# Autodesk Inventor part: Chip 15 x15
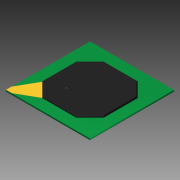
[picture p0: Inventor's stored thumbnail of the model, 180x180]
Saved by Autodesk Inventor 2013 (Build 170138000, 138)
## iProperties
Company: Autodesk Inc.
Created: 2005-12
Part Number: Chip 15 x15
Document SubType Name: Modeling
Designer: Autodesk Inc.
Density: 1 g/cm^3
Mass: 0.665599 g
Surface Area: 18.8536 cm^2
Volume: 0.665599 cm^3
Material: Allgemein
Title: Personal Computer
Author: Autodesk Inc.
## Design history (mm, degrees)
sketch "Sketch1"
  geometry: L1 (0, 21)-(0, -21) reference; L2 (-21, 0)-(21, 0) reference; L3 (-15, 15)-(15, 15); L4 (15, 15)-(15, -15); L5 (15, -15)-(-15, -15); L6 (-15, -15)-(-15, 15)
  constraints: 8 end point, 2 parallel, 2 perpendicular, 1 horizontal, 2 other
  dimensions: "d0" = 30 distance of L3.start L3.end
extrude "Extrusion1" new body sketch "Sketch1" distance "d1" = 0.5; taper "d2" = 0 deg
sketch "Sketch2"
  geometry: L1 (0, 21)-(0, -21) reference; L2 (-21, 0)-(21, 0) reference; L3 (-11, 11)-(11, 11); L4 (11, 11)-(11, -11); L5 (11, -11)-(-11, -11); L6 (-11, -11)-(-11, 11)
  constraints: 8 end point, 2 parallel, 2 perpendicular, 1 horizontal, 2 other
  dimensions: "d3" = 22 distance of L3.start L3.end
extrude "Extrusion2" join sketch "Sketch2" distance "d4" = 0.5; taper "d5" = 0 deg
chamfer "Chamfer1" distance "d6" = 5; stored, may be unused: second distance "d7" = 2, angle "d8" = 45 deg
chamfer "Chamfer2" distance "d9" = 0.3; stored, may be unused: second distance "d10" = 2, angle "d11" = 45 deg
sketch "Sketch3"
  geometry: L1 (-11, -6)-(-6, -11) reference; L2 (-15, -15)-(-15, 15) reference; L3 (15, -15)-(-15, -15) reference; L4 (-11, -6)-(-15, -13); L5 (-6, -11)-(-13, -15)
  constraints: 4 end point, 2 point on line
  dimensions: "d12" = 2 distance from line of L2 L5.end; "d13" = 2 distance from line of L3 L4.end (= d12)
extrude "Extrusion3" join sketch "Sketch3" distance "d14" = 0.05; taper "d15" = 0 deg
sketch "Sketch4"
  geometry: C1 r 0.25 at (-4.215, -4.222)
  constraints: 1 centre point
  dimensions: "d16" = 0.5 diameter of C1
extrude "Extrusion4" cut sketch "Sketch4" distance "d17" = 0.1; taper "d18" = 0 deg
body "Solid1"
fillet "Fillet1" dims "d20" = 0.1
